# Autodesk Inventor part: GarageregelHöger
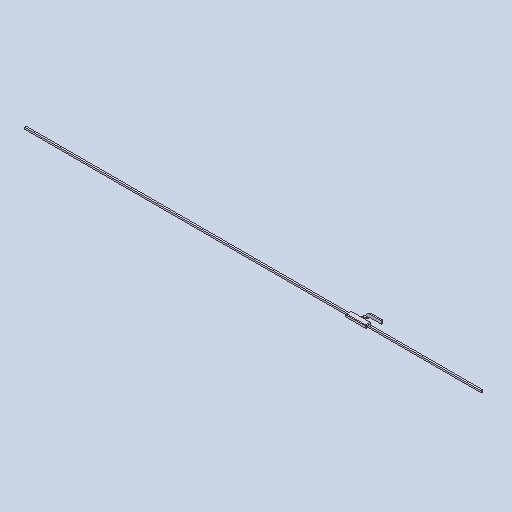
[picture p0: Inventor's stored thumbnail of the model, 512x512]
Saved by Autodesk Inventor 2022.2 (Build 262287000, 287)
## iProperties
Created: 2019-06
Part Number: GarageregelHöger
Material: Aluminum 6061, Welded
Document SubType Name: Modeling
Designer: cl
Density: 2.7 g/cm^3
Appearance: Weld - Aluminum
Author: cl
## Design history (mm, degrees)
sketch "Sketch1"
  geometry: L1 (5, 0)-(175, 0); L2 (180, -5)-(180, -45); L3 (175, -50)-(5, -50); L4 (0, -45)-(0, -5); L5 (0, -61.45)-(0, 11.45) reference; L6 (217.45, 0)-(-37.45, 0) reference; A1 r 5 centre (175, -5) between (180, -5) and (175, 0); A2 r 5 centre (175, -45) between (175, -50) and (180, -45); A3 r 5 centre (5, -45) between (0, -45) and (5, -50); A4 r 5 centre (5, -5) between (5, 0) and (0, -5); 5 further points
  constraints: 8 end point, 8 point on circle, 8 point on line, 8 tangent, 4 centre point, 3 equal radius, 2 collinear, 2 parallel, 1 horizontal, 1 perpendicular
  dimensions: "d0" = 180 distance of point (180, -50) point (0, -50); "d1" = 50 distance of point (180, 0) point (180, -50); "d2" = 5 radius of A1
extrude "Extrusion1" new body sketch "Sketch1" distance "d3" = 22; taper "d4" = 0 deg
fillet "Fillet1" dims "d5" = 5
workplane "Work Plane1"
sketch "Sketch2"
  geometry: L1 (73.892, -50)-(52.54, -75.446); L2 (52.54, -75.446)-(67.861, -88.302); L3 (67.861, -88.302)-(100, -50); L4 (180, -45)-(180, -5) reference; L5 (5, -50)-(175, -50) reference; 1 further point
  constraints: 6 end point, 2 point on line, 1 parallel, 1 perpendicular
  dimensions: "d8" = 50 distance of L2.end L3.end; "d9" = 20 distance between parallel lines of L3 L1; "d10" = 80 distance from line of L4 L3.end; "d11" = 130 deg angle of L5 L3
extrude "Extrusion2" join sketch "Sketch2" distance "d12" = 10; taper "d13" = 0 deg
sketch "Sketch3"
  geometry: L1 (-67.861, -88.302)-(-100, -50) reference; L2 (-78.648, -75.446)-(-53.648, -75.446); L3 (-38.648, -75.446)-(-38.648, -88.302); L4 (-38.648, -88.302)-(-53.648, -88.302); L5 (-78.648, -88.302)-(-78.648, -75.446); L6 (-53.648, -75.446)-(-53.648, -88.302); L7 (-53.648, -88.302)-(-78.648, -88.302); L8 (-53.648, -75.446)-(-38.648, -75.446); 3 further points
  constraints: 14 end point, 5 parallel, 5 point on line, 4 perpendicular, 2 horizontal
  dimensions: "d16" = 25 distance between parallel lines of L5 L6; "d17" = 40 distance between parallel lines of L5 L3
revolve "Revolution1" sketch "Sketch3" stored, may be unused: angle "d18" = 90 deg
fillet "Fillet2" dims "d19" = 2
fillet "Fillet3" dims "d20" = 2
sketch "Sketch4"
  geometry: L1 (0, 25)-(0, 0) reference; L2 (0, 0)-(12.856, 0) reference; L3 (12.856, 0)-(12.856, 25) reference; L4 (12.856, 25)-(0, 25) reference; 1 further point
extrude "Extrusion3" join sketch "Sketch4" distance "d21" = 100; taper "d22" = 0 deg
sketch "Sketch5"
  geometry: L1 (40, 0)-(0, 0) reference; L2 (27.5, 0)-(12.5, 0); L3 (12.5, 0)-(12.5, 15); L4 (12.5, 15)-(27.5, 15); L5 (27.5, 15)-(27.5, 0); L6 (45, 0)-(45, 17) reference
  constraints: 8 end point, 2 parallel, 1 horizontal, 1 perpendicular, 1 point on line
  dimensions: "d23" = 15 distance of L3.end L4.end; "d24" = 15 distance of L2.end L3.end; "d25" = 17.5 distance between parallel lines of L5 L6
extrude "Extrusion4" join sketch "Sketch5" distance "d26" = 2845 (computed from Daghöjd_1); taper "d28" = 0 deg; dims "d27" = 1180, "d29" = 0
body "Solid1"
node "Projected Loop1"
other parameters: "d6" = 11, "BladBredd" = 987.5, "Fönsterhöjd" = 862
